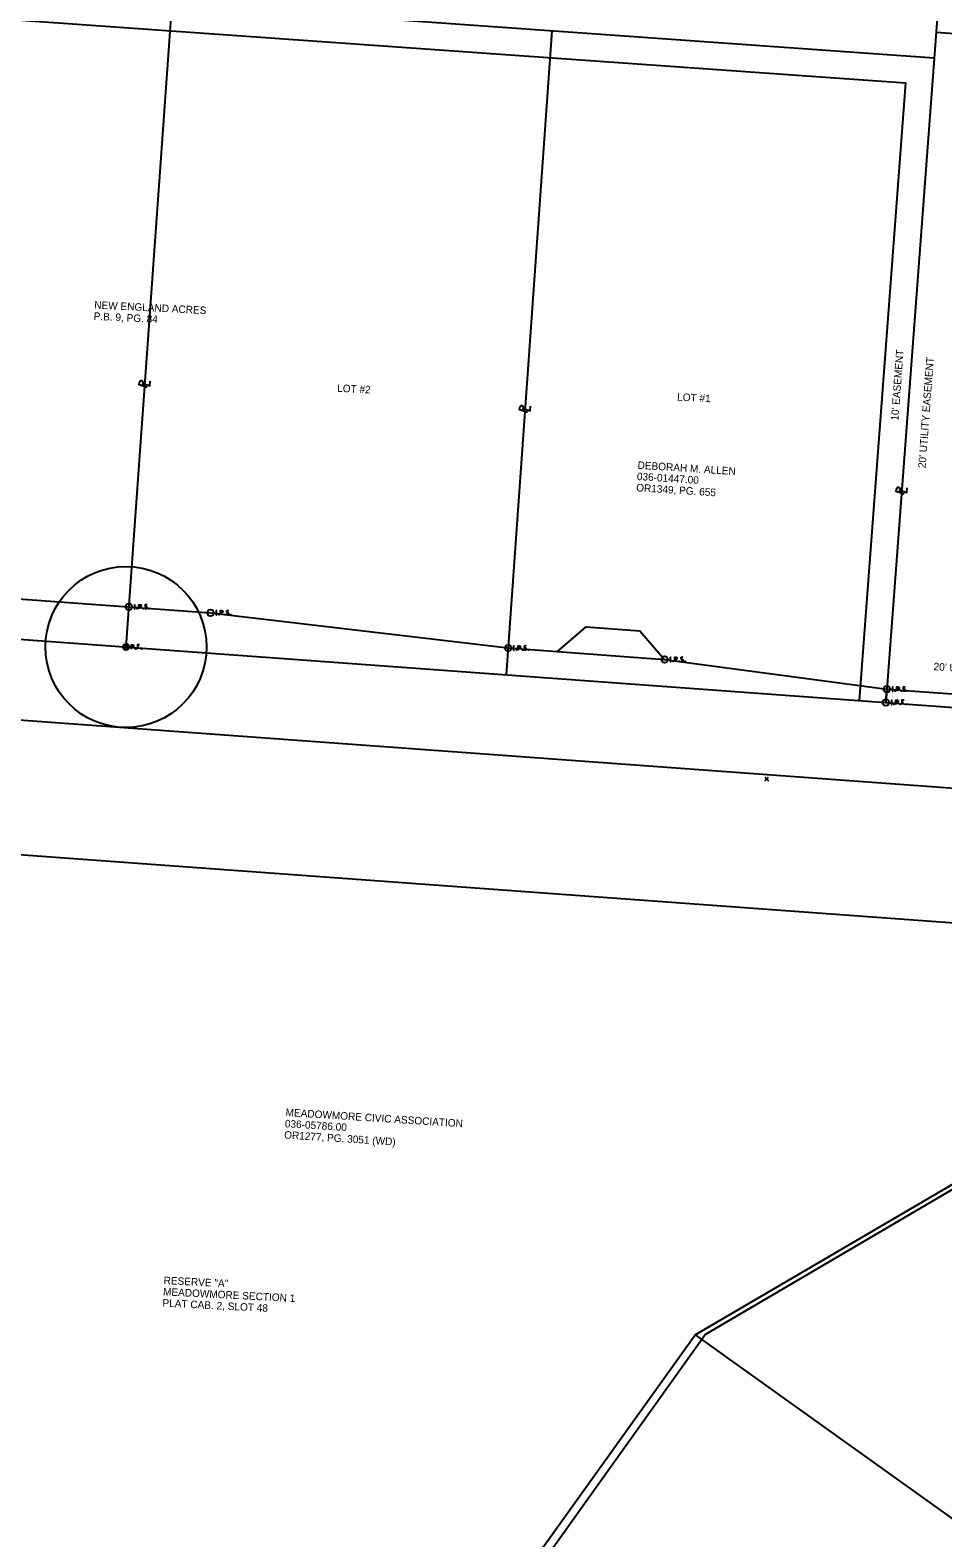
# Model space of a CAD drawing. Extents: x 1898254 to 1901377, y 701554 to 704886.
# Drawn here: x 1899893 to 1900233, y 702920 to 703481 of the extents above; entities that cross this region are included whole.
import ezdxf

# ---------------------------------------------------------------- set-up
doc = ezdxf.new("R2010")
doc.units = 0
for name, color, linetype in [('_CIVIL_CONSTRUCTION', 7, 'Continuous'), ('DV_X_Property_Line', 7, 'Continuous'), ('DV_X_Text', 7, 'Continuous'), ('PF_X_Ground_Line', 7, 'Continuous'), ('RW_X_CL', 7, 'Continuous'), ('RW_X_Esmt_U', 7, 'Continuous'), ('RW_X_Fee_RW', 7, 'Continuous'), ('SC_Scratch1', 7, 'Continuous'), ('SC_Scratch2', 7, 'Continuous'), ('SC_Scratch5', 7, 'Continuous'), ('SC_Scratch6', 7, 'Continuous'), ('SC_Scratch9', 7, 'Continuous'), ('SV_P_Mon_Cells_Set', 7, 'Continuous'), ('SV_X_Mon_Cells_Found', 7, 'Continuous'), ('SV_X_Random_Point', 7, 'Continuous')]:
    doc.layers.add(name, color=color, linetype=linetype)

msp = doc.modelspace()

# ---------------------------------------------------------------- linework, layer by layer
at = {"layer": '_CIVIL_CONSTRUCTION'}
for points in [[(1900089.85, 703249.91), (1900100.56, 703259.15), (1900120.5, 703257.7), (1900129.75, 703246.99)], [(1900212.15, 703230.94), (1900212.52, 703235.93), (1900249.06, 703233.26), (1900279.35, 703236.06), (1900314.63, 703233.48), (1900328.85, 703227.43), (1900415.98, 703221.06), (1900415.61, 703216.07)]]:
    msp.add_lwpolyline(points, dxfattribs=at)
at = {"layer": 'DV_X_Property_Line'}
for p, q in [((1900230.14, 703471.05), (1899662.55, 703511.42)), ((1900233.17, 703511.4), (1900212.15, 703230.94)), ((1899946.13, 703491.25), (1899929.09, 703251.63)), ((1900087.78, 703481.18), (1900070.72, 703241.28)), ((1900230.87, 703480.71), (1900642.66, 703450.49)), ((1899935.38, 703348.8), (1899935.47, 703350.1)), ((1899936.06, 703349.56), (1899936.06, 703349.56)), ((1900077.08, 703339.51), (1900077.17, 703340.8)), ((1900077.76, 703340.26), (1900077.76, 703340.26)), ((1900217.38, 703309.08), (1900217.48, 703310.38)), ((1900218.06, 703309.84), (1900218.06, 703309.84))]:
    msp.add_line(p, q, dxfattribs=at)
for points in [[(1899936.94, 703348.27), (1899934.04, 703349.26), (1899934.11, 703350.29)], [(1899935.12, 703349.89), (1899938.01, 703348.89), (1899938.14, 703350.63)], [(1900078.64, 703338.97), (1900075.73, 703339.96), (1900075.81, 703341)], [(1900076.82, 703340.6), (1900079.71, 703339.6), (1900079.83, 703341.34)], [(1900218.94, 703308.55), (1900216.04, 703309.55), (1900216.12, 703310.58)], [(1900217.12, 703310.17), (1900220.01, 703309.16), (1900220.14, 703310.91)]]:
    msp.add_lwpolyline(points, dxfattribs=at)
for centre, start, end in [((1899934.78, 703350.14), 356.4035, 167.2606), ((1900076.48, 703340.84), 356.4035, 167.2606), ((1900216.79, 703310.42), 356.1849, 167.042)]:
    msp.add_arc(centre, 0.69, start, end, dxfattribs=at)
at = {"layer": 'PF_X_Ground_Line'}
msp.add_lwpolyline([(1899647.24, 703291.95), (1899701.15, 703283.1), (1899819.04, 703274.72), (1899960.56, 703264.37), (1900071.43, 703251.26), (1900129.75, 703246.99), (1900212.52, 703235.93), (1900212.15, 703230.94)], dxfattribs=at)
at = {"layer": 'RW_X_CL'}
msp.add_line((1899815.76, 703229.84), (1901162.17, 703131.42), dxfattribs=at)
at = {"layer": 'RW_X_Esmt_U'}
msp.add_lwpolyline([(1899661.84, 703501.44), (1900219.42, 703461.79), (1900202.18, 703231.69)], dxfattribs=at)
at = {"layer": 'RW_X_Fee_RW'}
for p, q in [((1899817.89, 703259.76), (1900604.1, 703202.29)), ((1899868.13, 703175.88), (1900606.62, 703121.9))]:
    msp.add_line(p, q, dxfattribs=at)
at = {"layer": 'SC_Scratch1'}
msp.add_circle((1899929.09, 703251.63), 30, dxfattribs=at)
at = {"layer": 'SC_Scratch2'}
msp.add_circle((1899815.76, 703229.84), 1561.35, dxfattribs=at)
at = {"layer": 'SC_Scratch5'}
for p, q in [((1899817.89, 703259.76), (1900604.1, 703202.29)), ((1899868.13, 703175.88), (1900606.62, 703121.9))]:
    msp.add_line(p, q, dxfattribs=at)
for points in [[(1899647.24, 703291.95), (1899701.15, 703283.1), (1899819.04, 703274.72), (1899960.56, 703264.37), (1900071.43, 703251.26), (1900129.75, 703246.99), (1900212.52, 703235.93), (1900212.15, 703230.94)], [(1900089.85, 703249.91), (1900100.56, 703259.15), (1900120.5, 703257.7), (1900129.75, 703246.99)], [(1900212.15, 703230.94), (1900212.52, 703235.93), (1900249.06, 703233.26), (1900279.35, 703236.06), (1900314.63, 703233.48), (1900328.85, 703227.43), (1900415.98, 703221.06), (1900415.61, 703216.07)]]:
    msp.add_lwpolyline(points, dxfattribs=at)
at = {"layer": 'SC_Scratch6'}
for p, q in [((1900144.84, 702995.46), (1900387.35, 703137.92)), ((1900003.06, 702797.06), (1900144.84, 702995.46))]:
    msp.add_line(p, q, dxfattribs=at)
at = {"layer": 'SC_Scratch9'}
for p, q in [((1900141.16, 702995.38), (1900384.72, 703138.12)), ((1899999.17, 702797.13), (1900141.16, 702995.38)), ((1900141.16, 702995.38), (1900324.05, 702864.31))]:
    msp.add_line(p, q, dxfattribs=at)
at = {"layer": 'SV_P_Mon_Cells_Set'}
for points in [[(1899932.18, 703267.4), (1899932.53, 703267.4)], [(1899932.18, 703265.8), (1899932.53, 703265.8)], [(1899932.35, 703265.8), (1899932.35, 703267.4)], [(1899933.31, 703266.01), (1899933.37, 703266.01), (1899933.4, 703265.99), (1899933.43, 703265.94), (1899933.43, 703265.87), (1899933.4, 703265.82), (1899933.37, 703265.8), (1899933.31, 703265.8), (1899933.28, 703265.82), (1899933.25, 703265.87), (1899933.25, 703265.94), (1899933.28, 703265.99), (1899933.31, 703266.01)], [(1899933.92, 703265.8), (1899933.92, 703267.4), (1899934.45, 703267.4), (1899934.5, 703267.39), (1899934.58, 703267.36), (1899934.61, 703267.34), (1899934.65, 703267.31), (1899934.69, 703267.25), (1899934.72, 703267.18), (1899934.75, 703267.08), (1899934.75, 703266.93), (1899934.74, 703266.88), (1899934.71, 703266.81), (1899934.67, 703266.72), (1899934.62, 703266.68), (1899934.59, 703266.66), (1899934.54, 703266.63), (1899934.45, 703266.62), (1899933.92, 703266.62)], [(1899935.56, 703266.01), (1899935.62, 703266.01), (1899935.65, 703265.99), (1899935.68, 703265.94), (1899935.68, 703265.87), (1899935.65, 703265.82), (1899935.62, 703265.8), (1899935.56, 703265.8), (1899935.53, 703265.82), (1899935.5, 703265.87), (1899935.5, 703265.94), (1899935.53, 703265.99), (1899935.56, 703266.01)], [(1899936.93, 703267.29), (1899936.91, 703267.31), (1899936.87, 703267.34), (1899936.77, 703267.37), (1899936.65, 703267.4), (1899936.56, 703267.4), (1899936.53, 703267.4), (1899936.39, 703267.36), (1899936.27, 703267.29), (1899936.19, 703267.18), (1899936.17, 703267.08), (1899936.17, 703267.01), (1899936.19, 703266.91), (1899936.28, 703266.82), (1899936.88, 703266.44), (1899936.94, 703266.39), (1899936.96, 703266.34), (1899936.98, 703266.26), (1899936.98, 703266.19), (1899936.97, 703266.11), (1899936.96, 703266.06), (1899936.94, 703266), (1899936.92, 703265.95), (1899936.9, 703265.91), (1899936.86, 703265.87), (1899936.83, 703265.85), (1899936.79, 703265.82), (1899936.75, 703265.81), (1899936.65, 703265.8), (1899936.5, 703265.8), (1899936.4, 703265.82), (1899936.26, 703265.91), (1899936.17, 703265.99)], [(1899937.74, 703266.01), (1899937.8, 703266.01), (1899937.83, 703265.99), (1899937.87, 703265.94), (1899937.87, 703265.87), (1899937.83, 703265.82), (1899937.8, 703265.8), (1899937.74, 703265.8), (1899937.71, 703265.82), (1899937.68, 703265.87), (1899937.68, 703265.94), (1899937.71, 703265.99), (1899937.74, 703266.01)], [(1899962.58, 703265.18), (1899962.94, 703265.18)], [(1899962.76, 703263.58), (1899962.76, 703265.18)], [(1899964.33, 703263.58), (1899964.33, 703265.18), (1899964.85, 703265.18), (1899964.91, 703265.16), (1899964.99, 703265.14), (1899965.02, 703265.11), (1899965.05, 703265.09), (1899965.1, 703265.02), (1899965.13, 703264.96), (1899965.15, 703264.86), (1899965.15, 703264.71), (1899965.14, 703264.66), (1899965.12, 703264.58), (1899965.08, 703264.5), (1899965.03, 703264.46), (1899965, 703264.43), (1899964.94, 703264.41), (1899964.85, 703264.39), (1899964.33, 703264.39)], [(1899967.33, 703265.06), (1899967.31, 703265.09), (1899967.28, 703265.11), (1899967.18, 703265.15), (1899967.06, 703265.18), (1899966.97, 703265.18), (1899966.94, 703265.18), (1899966.79, 703265.14), (1899966.67, 703265.06), (1899966.6, 703264.96), (1899966.57, 703264.86), (1899966.57, 703264.79), (1899966.6, 703264.68), (1899966.68, 703264.6), (1899967.29, 703264.22), (1899967.35, 703264.17), (1899967.37, 703264.12), (1899967.39, 703264.04), (1899967.39, 703263.97), (1899967.38, 703263.89), (1899967.37, 703263.84), (1899967.35, 703263.78), (1899967.32, 703263.73), (1899967.3, 703263.69), (1899967.27, 703263.65), (1899967.24, 703263.63), (1899967.19, 703263.6), (1899967.16, 703263.59), (1899967.06, 703263.58), (1899966.9, 703263.58), (1899966.81, 703263.6), (1899966.66, 703263.69), (1899966.57, 703263.76)], [(1899962.58, 703263.58), (1899962.94, 703263.58)], [(1899963.72, 703263.79), (1899963.77, 703263.79), (1899963.81, 703263.76), (1899963.84, 703263.71), (1899963.84, 703263.65), (1899963.81, 703263.6), (1899963.77, 703263.58), (1899963.72, 703263.58), (1899963.69, 703263.6), (1899963.65, 703263.65), (1899963.65, 703263.71), (1899963.69, 703263.76), (1899963.72, 703263.79)], [(1899965.97, 703263.79), (1899966.02, 703263.79), (1899966.06, 703263.76), (1899966.09, 703263.71), (1899966.09, 703263.65), (1899966.06, 703263.6), (1899966.02, 703263.58), (1899965.97, 703263.58), (1899965.93, 703263.6), (1899965.9, 703263.65), (1899965.9, 703263.71), (1899965.93, 703263.76), (1899965.97, 703263.79)], [(1899968.15, 703263.79), (1899968.21, 703263.79), (1899968.24, 703263.76), (1899968.27, 703263.71), (1899968.27, 703263.65), (1899968.24, 703263.6), (1899968.21, 703263.58), (1899968.15, 703263.58), (1899968.12, 703263.6), (1899968.08, 703263.65), (1899968.08, 703263.71), (1899968.12, 703263.76), (1899968.15, 703263.79)], [(1900073.45, 703252.06), (1900073.8, 703252.06)], [(1900073.45, 703250.46), (1900073.8, 703250.46)], [(1900073.62, 703250.46), (1900073.62, 703252.06)], [(1900074.58, 703250.67), (1900074.64, 703250.67), (1900074.67, 703250.65), (1900074.7, 703250.6), (1900074.7, 703250.53), (1900074.67, 703250.48), (1900074.64, 703250.46), (1900074.58, 703250.46), (1900074.55, 703250.48), (1900074.51, 703250.53), (1900074.51, 703250.6), (1900074.55, 703250.65), (1900074.58, 703250.67)], [(1900075.19, 703250.46), (1900075.19, 703252.06), (1900075.72, 703252.06), (1900075.77, 703252.05), (1900075.85, 703252.02), (1900075.88, 703252), (1900075.91, 703251.97), (1900075.96, 703251.91), (1900075.99, 703251.84), (1900076.01, 703251.74), (1900076.01, 703251.59), (1900076, 703251.54), (1900075.98, 703251.47), (1900075.94, 703251.38), (1900075.89, 703251.34), (1900075.86, 703251.32), (1900075.8, 703251.29), (1900075.72, 703251.28), (1900075.19, 703251.28)], [(1900076.83, 703250.67), (1900076.88, 703250.67), (1900076.92, 703250.65), (1900076.95, 703250.6), (1900076.95, 703250.53), (1900076.92, 703250.48), (1900076.88, 703250.46), (1900076.83, 703250.46), (1900076.8, 703250.48), (1900076.76, 703250.53), (1900076.76, 703250.6), (1900076.8, 703250.65), (1900076.83, 703250.67)], [(1900078.2, 703251.95), (1900078.17, 703251.97), (1900078.14, 703252), (1900078.04, 703252.03), (1900077.92, 703252.06), (1900077.83, 703252.06), (1900077.8, 703252.06), (1900077.66, 703252.02), (1900077.54, 703251.95), (1900077.46, 703251.84), (1900077.44, 703251.74), (1900077.44, 703251.67), (1900077.46, 703251.57), (1900077.55, 703251.48), (1900078.15, 703251.1), (1900078.21, 703251.05), (1900078.23, 703251), (1900078.25, 703250.92), (1900078.25, 703250.85), (1900078.24, 703250.77), (1900078.23, 703250.72), (1900078.21, 703250.66), (1900078.19, 703250.61), (1900078.16, 703250.57), (1900078.13, 703250.53), (1900078.1, 703250.51), (1900078.05, 703250.48), (1900078.02, 703250.47), (1900077.92, 703250.46), (1900077.77, 703250.46), (1900077.67, 703250.48), (1900077.52, 703250.57), (1900077.44, 703250.65)], [(1900079.01, 703250.67), (1900079.07, 703250.67), (1900079.1, 703250.65), (1900079.13, 703250.6), (1900079.13, 703250.53), (1900079.1, 703250.48), (1900079.07, 703250.46), (1900079.01, 703250.46), (1900078.98, 703250.48), (1900078.95, 703250.53), (1900078.95, 703250.6), (1900078.98, 703250.65), (1900079.01, 703250.67)], [(1900131.77, 703247.8), (1900132.12, 703247.8)], [(1900131.77, 703246.2), (1900132.12, 703246.2)], [(1900131.94, 703246.2), (1900131.94, 703247.8)], [(1900132.9, 703246.41), (1900132.96, 703246.41), (1900132.99, 703246.38), (1900133.02, 703246.33), (1900133.02, 703246.27), (1900132.99, 703246.22), (1900132.96, 703246.2), (1900132.9, 703246.2), (1900132.87, 703246.22), (1900132.84, 703246.27), (1900132.84, 703246.33), (1900132.87, 703246.38), (1900132.9, 703246.41)], [(1900133.51, 703246.2), (1900133.51, 703247.8), (1900134.04, 703247.8), (1900134.09, 703247.78), (1900134.17, 703247.76), (1900134.2, 703247.73), (1900134.24, 703247.71), (1900134.28, 703247.64), (1900134.31, 703247.58), (1900134.33, 703247.48), (1900134.33, 703247.33), (1900134.32, 703247.28), (1900134.3, 703247.2), (1900134.26, 703247.12), (1900134.21, 703247.08), (1900134.18, 703247.05), (1900134.13, 703247.03), (1900134.04, 703247.01), (1900133.51, 703247.01)], [(1900135.15, 703246.41), (1900135.21, 703246.41), (1900135.24, 703246.38), (1900135.27, 703246.33), (1900135.27, 703246.27), (1900135.24, 703246.22), (1900135.21, 703246.2), (1900135.15, 703246.2), (1900135.12, 703246.22), (1900135.08, 703246.27), (1900135.08, 703246.33), (1900135.12, 703246.38), (1900135.15, 703246.41)], [(1900136.52, 703247.68), (1900136.5, 703247.71), (1900136.46, 703247.73), (1900136.36, 703247.77), (1900136.24, 703247.8), (1900136.15, 703247.8), (1900136.12, 703247.8), (1900135.98, 703247.76), (1900135.86, 703247.68), (1900135.78, 703247.58), (1900135.76, 703247.48), (1900135.76, 703247.4), (1900135.78, 703247.3), (1900135.87, 703247.22), (1900136.47, 703246.84), (1900136.53, 703246.79), (1900136.55, 703246.74), (1900136.57, 703246.66), (1900136.57, 703246.59), (1900136.56, 703246.51), (1900136.55, 703246.46), (1900136.53, 703246.4), (1900136.51, 703246.35), (1900136.48, 703246.31), (1900136.45, 703246.27), (1900136.42, 703246.25), (1900136.37, 703246.22), (1900136.34, 703246.21), (1900136.24, 703246.2), (1900136.09, 703246.2), (1900135.99, 703246.22), (1900135.84, 703246.31), (1900135.76, 703246.38)], [(1900137.33, 703246.41), (1900137.39, 703246.41), (1900137.42, 703246.38), (1900137.45, 703246.33), (1900137.45, 703246.27), (1900137.42, 703246.22), (1900137.39, 703246.2), (1900137.33, 703246.2), (1900137.3, 703246.22), (1900137.27, 703246.27), (1900137.27, 703246.33), (1900137.3, 703246.38), (1900137.33, 703246.41)], [(1900214.54, 703236.73), (1900214.89, 703236.73)], [(1900214.54, 703235.13), (1900214.89, 703235.13)], [(1900214.72, 703235.13), (1900214.72, 703236.73)], [(1900215.68, 703235.35), (1900215.73, 703235.35), (1900215.77, 703235.32), (1900215.8, 703235.27), (1900215.8, 703235.21), (1900215.77, 703235.16), (1900215.73, 703235.13), (1900215.68, 703235.13), (1900215.64, 703235.16), (1900215.61, 703235.21), (1900215.61, 703235.27), (1900215.64, 703235.32), (1900215.68, 703235.35)], [(1900216.28, 703235.13), (1900216.28, 703236.73), (1900216.81, 703236.73), (1900216.87, 703236.72), (1900216.95, 703236.69), (1900216.98, 703236.67), (1900217.01, 703236.64), (1900217.06, 703236.58), (1900217.09, 703236.52), (1900217.11, 703236.42), (1900217.11, 703236.27), (1900217.1, 703236.21), (1900217.08, 703236.14), (1900217.03, 703236.05), (1900216.99, 703236.01), (1900216.96, 703235.99), (1900216.9, 703235.96), (1900216.81, 703235.95), (1900216.28, 703235.95)], [(1900217.93, 703235.35), (1900217.98, 703235.35), (1900218.01, 703235.32), (1900218.05, 703235.27), (1900218.05, 703235.21), (1900218.01, 703235.16), (1900217.98, 703235.13), (1900217.93, 703235.13), (1900217.89, 703235.16), (1900217.86, 703235.21), (1900217.86, 703235.27), (1900217.89, 703235.32), (1900217.93, 703235.35)], [(1900219.29, 703236.62), (1900219.27, 703236.64), (1900219.24, 703236.67), (1900219.14, 703236.71), (1900219.02, 703236.73), (1900218.93, 703236.73), (1900218.9, 703236.73), (1900218.75, 703236.69), (1900218.63, 703236.62), (1900218.55, 703236.52), (1900218.53, 703236.42), (1900218.53, 703236.34), (1900218.55, 703236.24), (1900218.64, 703236.15), (1900219.25, 703235.77), (1900219.3, 703235.72), (1900219.33, 703235.67), (1900219.35, 703235.6), (1900219.35, 703235.52), (1900219.34, 703235.45), (1900219.33, 703235.4), (1900219.3, 703235.33), (1900219.28, 703235.28), (1900219.26, 703235.24), (1900219.23, 703235.21), (1900219.19, 703235.18), (1900219.15, 703235.16), (1900219.12, 703235.14), (1900219.02, 703235.13), (1900218.86, 703235.13), (1900218.76, 703235.16), (1900218.62, 703235.24), (1900218.53, 703235.32)], [(1900220.11, 703235.35), (1900220.16, 703235.35), (1900220.2, 703235.32), (1900220.23, 703235.27), (1900220.23, 703235.21), (1900220.2, 703235.16), (1900220.16, 703235.13), (1900220.11, 703235.13), (1900220.08, 703235.16), (1900220.04, 703235.21), (1900220.04, 703235.27), (1900220.08, 703235.32), (1900220.11, 703235.35)]]:
    msp.add_lwpolyline(points, dxfattribs=at)
for centre in [(1899930.16, 703266.6), (1899960.56, 703264.37), (1900071.43, 703251.26), (1900129.75, 703246.99), (1900212.52, 703235.93)]:
    msp.add_circle(centre, 1.2, dxfattribs=at)
at = {"layer": 'SV_X_Mon_Cells_Found'}
for points in [[(1899931.09, 703250.83), (1899931.09, 703252.43), (1899931.62, 703252.43), (1899931.68, 703252.42), (1899931.75, 703252.4), (1899931.79, 703252.37), (1899931.82, 703252.35), (1899931.86, 703252.28), (1899931.9, 703252.22), (1899931.92, 703252.12), (1899931.92, 703251.97), (1899931.91, 703251.92), (1899931.89, 703251.84), (1899931.84, 703251.75), (1899931.8, 703251.72), (1899931.76, 703251.69), (1899931.71, 703251.67), (1899931.62, 703251.65), (1899931.09, 703251.65)], [(1899932.73, 703251.05), (1899932.79, 703251.05), (1899932.82, 703251.02), (1899932.86, 703250.97), (1899932.86, 703250.91), (1899932.82, 703250.86), (1899932.79, 703250.83), (1899932.73, 703250.83), (1899932.7, 703250.86), (1899932.67, 703250.91), (1899932.67, 703250.97), (1899932.7, 703251.02), (1899932.73, 703251.05)], [(1899934.1, 703252.43), (1899933.34, 703252.43), (1899933.34, 703250.83)], [(1899933.34, 703251.65), (1899933.88, 703251.65)], [(1899934.88, 703251.05), (1899934.94, 703251.05), (1899934.97, 703251.02), (1899935.01, 703250.97), (1899935.01, 703250.91), (1899934.97, 703250.86), (1899934.94, 703250.83), (1899934.88, 703250.83), (1899934.85, 703250.86), (1899934.82, 703250.91), (1899934.82, 703250.97), (1899934.85, 703251.02), (1899934.88, 703251.05)], [(1900214.17, 703231.77), (1900214.52, 703231.77)], [(1900214.34, 703230.17), (1900214.34, 703231.77)], [(1900215.91, 703230.17), (1900215.91, 703231.77), (1900216.44, 703231.77), (1900216.49, 703231.75), (1900216.57, 703231.73), (1900216.6, 703231.7), (1900216.63, 703231.68), (1900216.68, 703231.62), (1900216.71, 703231.55), (1900216.73, 703231.45), (1900216.73, 703231.3), (1900216.72, 703231.25), (1900216.7, 703231.18), (1900216.66, 703231.09), (1900216.61, 703231.05), (1900216.58, 703231.02), (1900216.52, 703231), (1900216.44, 703230.99), (1900215.91, 703230.99)], [(1900218.92, 703231.77), (1900218.16, 703231.77), (1900218.16, 703230.17)], [(1900214.17, 703230.17), (1900214.52, 703230.17)], [(1900215.3, 703230.38), (1900215.36, 703230.38), (1900215.39, 703230.36), (1900215.42, 703230.31), (1900215.42, 703230.24), (1900215.39, 703230.19), (1900215.36, 703230.17), (1900215.3, 703230.17), (1900215.27, 703230.19), (1900215.23, 703230.24), (1900215.23, 703230.31), (1900215.27, 703230.36), (1900215.3, 703230.38)], [(1900217.55, 703230.38), (1900217.6, 703230.38), (1900217.64, 703230.36), (1900217.67, 703230.31), (1900217.67, 703230.24), (1900217.64, 703230.19), (1900217.6, 703230.17), (1900217.55, 703230.17), (1900217.52, 703230.19), (1900217.48, 703230.24), (1900217.48, 703230.31), (1900217.52, 703230.36), (1900217.55, 703230.38)], [(1900218.16, 703230.99), (1900218.7, 703230.99)], [(1900219.7, 703230.38), (1900219.75, 703230.38), (1900219.79, 703230.36), (1900219.82, 703230.31), (1900219.82, 703230.24), (1900219.79, 703230.19), (1900219.75, 703230.17), (1900219.7, 703230.17), (1900219.67, 703230.19), (1900219.63, 703230.24), (1900219.63, 703230.31), (1900219.67, 703230.36), (1900219.7, 703230.38)]]:
    msp.add_lwpolyline(points, dxfattribs=at)
for centre, radius in [((1899929.09, 703251.63), 1.2), ((1899929.09, 703251.63), 0.495), ((1900212.15, 703230.97), 1.2)]:
    msp.add_circle(centre, radius, dxfattribs=at)
at = {"layer": 'SV_X_Random_Point'}
for p, q in [((1900167.1, 703201.75), (1900168.43, 703203.08)), ((1900167.1, 703203.08), (1900168.43, 703201.75))]:
    msp.add_line(p, q, dxfattribs=at)

# ---------------------------------------------------------------- texts
at = {"layer": 'DV_X_Text'}
for s, rotation, p in [('NEW ENGLAND ACRES', 357.0949, (1899917.22, 703377.75)), ('P.B. 9, PG. 84', 357.0949, (1899917, 703373.55)), ("10' EASEMENT", 85.7139, (1900216.81, 703335.88)), ("20' UTILITY EASEMENT", 85.7139, (1900226.95, 703318.18)), ('LOT #2', 357.0949, (1900007.71, 703346.73)), ('LOT #1', 357.0949, (1900134.34, 703343.44)), ('036-01447.00', 356.3351, (1900119.33, 703313.86)), ('DEBORAH M. ALLEN', 356.3351, (1900119.6, 703318.05)), ('OR1349, PG. 655', 356.3351, (1900119.07, 703309.67)), ("20' UTILITY EASEMENT", 355.9325, (1900229.85, 703243.02)), ('036-05786.00', 356.3351, (1899988.21, 703072.72)), ('MEADOWMORE CIVIC ASSOCIATION', 356.3351, (1899988.48, 703076.91)), ('OR1277, PG. 3051 (WD)', 356.3351, (1899987.94, 703068.52)), ('MEADOWMORE SECTION 1', 357.0949, (1899942.84, 703010.08)), ('RESERVE "A"', 357.0949, (1899943.05, 703014.28)), ('PLAT CAB. 2, SLOT 48', 357.0949, (1899942.62, 703005.89))]:
    msp.add_text(s, height=2.8, rotation=rotation, dxfattribs=at).set_placement(p)

doc.saveas('drawing.dxf')
